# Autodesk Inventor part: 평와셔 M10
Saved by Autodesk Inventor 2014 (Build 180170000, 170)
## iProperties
Created: 2026-03
Part Number: 평와셔 M10
Material: 강철, 연강
Document SubType Name: Modeling
Designer: dg
Density: 7.86 g/cm^3
Appearance: 강철
Mass: 3.95087 g
Surface Area: 7.03717 cm^2
Volume: 0.502655 cm^3
Author: jhkim
Description: 평면 와셔
Creation Date: 2025-06-27
Sending System: Autodesk Inventor 2026
Preprocessor: ST-DEVELOPER v20.1
Author: dg
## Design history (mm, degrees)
node "평와셔 M101"
body "Solid1"
node "기준1"
